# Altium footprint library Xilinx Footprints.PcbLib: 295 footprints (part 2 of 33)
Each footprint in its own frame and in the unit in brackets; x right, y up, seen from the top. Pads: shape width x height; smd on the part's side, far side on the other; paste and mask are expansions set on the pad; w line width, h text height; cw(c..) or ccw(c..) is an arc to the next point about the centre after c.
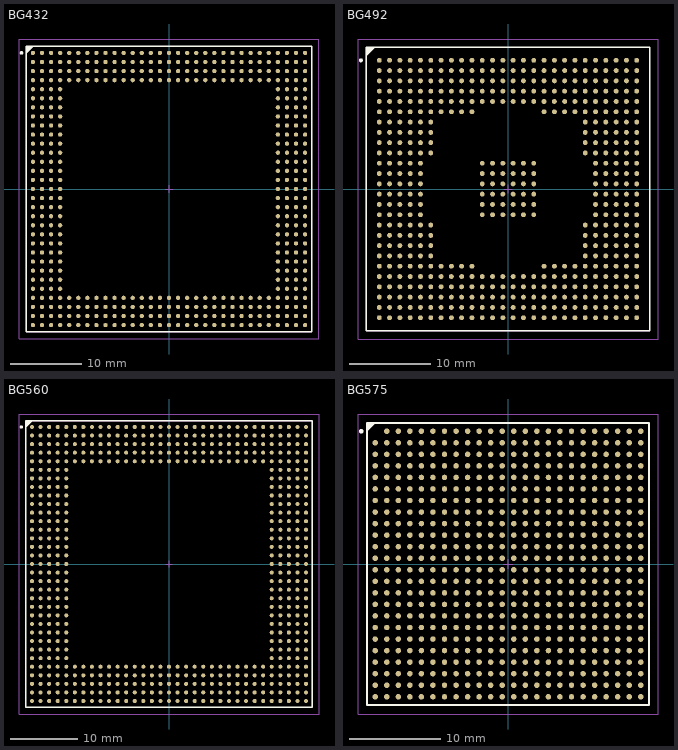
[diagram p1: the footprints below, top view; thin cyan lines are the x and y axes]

## BG432 [mm] "432-Ball Metal Ball Grid Array (BG432)"
height 1.7
pads (432):
  round 0.6 smd: A1(-19.05,19.05) A2(-17.78,19.05) A3(-16.51,19.05) A4(-15.24,19.05) A5(-13.97,19.05) A6(-12.7,19.05) A7(-11.43,19.05) A8(-10.16,19.05) A9(-8.89,19.05) A10(-7.62,19.05) A11(-6.35,19.05) A12(-5.08,19.05) A13(-3.81,19.05) A14(-2.54,19.05) A15(-1.27,19.05) A16(0,19.05) A17(1.27,19.05) A18(2.54,19.05) A19(3.81,19.05) A20(5.08,19.05) A21(6.35,19.05) A22(7.62,19.05) A23(8.89,19.05) A24(10.16,19.05) A25(11.43,19.05) A26(12.7,19.05) A27(13.97,19.05) A28(15.24,19.05) A29(16.51,19.05) A30(17.78,19.05) A31(19.05,19.05) AA1(-19.05,-6.35) AA2(-17.78,-6.35) AA3(-16.51,-6.35) AA4(-15.24,-6.35) AA28(15.24,-6.35) AA29(16.51,-6.35) AA30(17.78,-6.35) AA31(19.05,-6.35) AB1(-19.05,-7.62) AB2(-17.78,-7.62) AB3(-16.51,-7.62) AB4(-15.24,-7.62) AB28(15.24,-7.62) AB29(16.51,-7.62) AB30(17.78,-7.62) AB31(19.05,-7.62) AC1(-19.05,-8.89) AC2(-17.78,-8.89) AC3(-16.51,-8.89) AC4(-15.24,-8.89) AC28(15.24,-8.89) AC29(16.51,-8.89) AC30(17.78,-8.89) AC31(19.05,-8.89) AD1(-19.05,-10.16) AD2(-17.78,-10.16) AD3(-16.51,-10.16) AD4(-15.24,-10.16) AD28(15.24,-10.16) AD29(16.51,-10.16) AD30(17.78,-10.16) AD31(19.05,-10.16) AE1(-19.05,-11.43) AE2(-17.78,-11.43) AE3(-16.51,-11.43) AE4(-15.24,-11.43) AE28(15.24,-11.43) AE29(16.51,-11.43) AE30(17.78,-11.43) AE31(19.05,-11.43) AF1(-19.05,-12.7) AF2(-17.78,-12.7) AF3(-16.51,-12.7) AF4(-15.24,-12.7) AF28(15.24,-12.7) AF29(16.51,-12.7) AF30(17.78,-12.7) AF31(19.05,-12.7) AG1(-19.05,-13.97) AG2(-17.78,-13.97) AG3(-16.51,-13.97) AG4(-15.24,-13.97) AG28(15.24,-13.97) AG29(16.51,-13.97) AG30(17.78,-13.97) AG31(19.05,-13.97) AH1(-19.05,-15.24) AH2(-17.78,-15.24) AH3(-16.51,-15.24) AH4(-15.24,-15.24) AH5(-13.97,-15.24) AH6(-12.7,-15.24) AH7(-11.43,-15.24) AH8(-10.16,-15.24) AH9(-8.89,-15.24) AH10(-7.62,-15.24) AH11(-6.35,-15.24) AH12(-5.08,-15.24) AH13(-3.81,-15.24) AH14(-2.54,-15.24) AH15(-1.27,-15.24) AH16(0,-15.24) AH17(1.27,-15.24) AH18(2.54,-15.24) AH19(3.81,-15.24) AH20(5.08,-15.24) AH21(6.35,-15.24) AH22(7.62,-15.24) AH23(8.89,-15.24) AH24(10.16,-15.24) AH25(11.43,-15.24) AH26(12.7,-15.24) AH27(13.97,-15.24) AH28(15.24,-15.24) AH29(16.51,-15.24) AH30(17.78,-15.24) AH31(19.05,-15.24) AJ1(-19.05,-16.51) AJ2(-17.78,-16.51) AJ3(-16.51,-16.51) AJ4(-15.24,-16.51) AJ5(-13.97,-16.51) AJ6(-12.7,-16.51) AJ7(-11.43,-16.51) AJ8(-10.16,-16.51) AJ9(-8.89,-16.51) AJ10(-7.62,-16.51) AJ11(-6.35,-16.51) AJ12(-5.08,-16.51) AJ13(-3.81,-16.51) AJ14(-2.54,-16.51) AJ15(-1.27,-16.51) AJ16(0,-16.51) AJ17(1.27,-16.51) AJ18(2.54,-16.51) AJ19(3.81,-16.51) AJ20(5.08,-16.51) AJ21(6.35,-16.51) AJ22(7.62,-16.51) AJ23(8.89,-16.51) AJ24(10.16,-16.51) AJ25(11.43,-16.51) AJ26(12.7,-16.51) AJ27(13.97,-16.51) AJ28(15.24,-16.51) AJ29(16.51,-16.51) AJ30(17.78,-16.51) AJ31(19.05,-16.51) AK1(-19.05,-17.78) AK2(-17.78,-17.78) AK3(-16.51,-17.78) AK4(-15.24,-17.78) AK5(-13.97,-17.78) AK6(-12.7,-17.78) AK7(-11.43,-17.78) AK8(-10.16,-17.78) AK9(-8.89,-17.78) AK10(-7.62,-17.78) AK11(-6.35,-17.78) AK12(-5.08,-17.78) AK13(-3.81,-17.78) AK14(-2.54,-17.78) AK15(-1.27,-17.78) AK16(0,-17.78) AK17(1.27,-17.78) AK18(2.54,-17.78) AK19(3.81,-17.78) AK20(5.08,-17.78) AK21(6.35,-17.78) AK22(7.62,-17.78) AK23(8.89,-17.78) AK24(10.16,-17.78) AK25(11.43,-17.78) AK26(12.7,-17.78) AK27(13.97,-17.78) AK28(15.24,-17.78) AK29(16.51,-17.78) AK30(17.78,-17.78) AK31(19.05,-17.78) AL1(-19.05,-19.05) AL2(-17.78,-19.05) AL3(-16.51,-19.05) AL4(-15.24,-19.05) AL5(-13.97,-19.05) AL6(-12.7,-19.05) AL7(-11.43,-19.05) AL8(-10.16,-19.05) AL9(-8.89,-19.05) AL10(-7.62,-19.05) AL11(-6.35,-19.05) AL12(-5.08,-19.05) AL13(-3.81,-19.05) AL14(-2.54,-19.05) AL15(-1.27,-19.05) AL16(0,-19.05) AL17(1.27,-19.05) AL18(2.54,-19.05) AL19(3.81,-19.05) AL20(5.08,-19.05) AL21(6.35,-19.05) AL22(7.62,-19.05) AL23(8.89,-19.05) AL24(10.16,-19.05) AL25(11.43,-19.05) AL26(12.7,-19.05) AL27(13.97,-19.05) AL28(15.24,-19.05) AL29(16.51,-19.05) AL30(17.78,-19.05) AL31(19.05,-19.05) B1(-19.05,17.78) B2(-17.78,17.78) B3(-16.51,17.78) B4(-15.24,17.78) B5(-13.97,17.78) B6(-12.7,17.78) B7(-11.43,17.78) B8(-10.16,17.78) B9(-8.89,17.78) B10(-7.62,17.78) B11(-6.35,17.78) B12(-5.08,17.78) B13(-3.81,17.78) B14(-2.54,17.78) B15(-1.27,17.78) B16(0,17.78) B17(1.27,17.78) B18(2.54,17.78) B19(3.81,17.78) B20(5.08,17.78) B21(6.35,17.78) B22(7.62,17.78) B23(8.89,17.78) B24(10.16,17.78) B25(11.43,17.78) B26(12.7,17.78) B27(13.97,17.78) B28(15.24,17.78) B29(16.51,17.78) B30(17.78,17.78) B31(19.05,17.78) C1(-19.05,16.51) C2(-17.78,16.51) C3(-16.51,16.51) C4(-15.24,16.51) C5(-13.97,16.51) C6(-12.7,16.51) C7(-11.43,16.51) C8(-10.16,16.51) C9(-8.89,16.51) C10(-7.62,16.51) C11(-6.35,16.51) C12(-5.08,16.51) C13(-3.81,16.51) C14(-2.54,16.51) C15(-1.27,16.51) C16(0,16.51) C17(1.27,16.51) C18(2.54,16.51) C19(3.81,16.51) C20(5.08,16.51) C21(6.35,16.51) C22(7.62,16.51) C23(8.89,16.51) C24(10.16,16.51) C25(11.43,16.51) C26(12.7,16.51) C27(13.97,16.51) C28(15.24,16.51) C29(16.51,16.51) C30(17.78,16.51) C31(19.05,16.51) D1(-19.05,15.24) D2(-17.78,15.24) D3(-16.51,15.24) D4(-15.24,15.24) D5(-13.97,15.24) D6(-12.7,15.24) D7(-11.43,15.24) D8(-10.16,15.24) D9(-8.89,15.24) D10(-7.62,15.24) D11(-6.35,15.24) D12(-5.08,15.24) D13(-3.81,15.24) D14(-2.54,15.24) D15(-1.27,15.24) D16(0,15.24) D17(1.27,15.24) D18(2.54,15.24) D19(3.81,15.24) D20(5.08,15.24) D21(6.35,15.24) D22(7.62,15.24) D23(8.89,15.24) D24(10.16,15.24) D25(11.43,15.24) D26(12.7,15.24) D27(13.97,15.24) D28(15.24,15.24) D29(16.51,15.24) D30(17.78,15.24) D31(19.05,15.24) E1(-19.05,13.97) E2(-17.78,13.97) E3(-16.51,13.97) E4(-15.24,13.97) E28(15.24,13.97) E29(16.51,13.97) E30(17.78,13.97) E31(19.05,13.97) F1(-19.05,12.7) F2(-17.78,12.7) F3(-16.51,12.7) F4(-15.24,12.7) F28(15.24,12.7) F29(16.51,12.7) F30(17.78,12.7) F31(19.05,12.7) G1(-19.05,11.43) G2(-17.78,11.43) G3(-16.51,11.43) G4(-15.24,11.43) G28(15.24,11.43) G29(16.51,11.43) G30(17.78,11.43) G31(19.05,11.43) H1(-19.05,10.16) H2(-17.78,10.16) H3(-16.51,10.16) H4(-15.24,10.16) H28(15.24,10.16) H29(16.51,10.16) H30(17.78,10.16) H31(19.05,10.16) J1(-19.05,8.89) J2(-17.78,8.89) J3(-16.51,8.89) J4(-15.24,8.89) J28(15.24,8.89) J29(16.51,8.89) J30(17.78,8.89) J31(19.05,8.89) K1(-19.05,7.62) K2(-17.78,7.62) K3(-16.51,7.62) K4(-15.24,7.62) K28(15.24,7.62) K29(16.51,7.62) K30(17.78,7.62) K31(19.05,7.62) L1(-19.05,6.35) L2(-17.78,6.35) L3(-16.51,6.35) L4(-15.24,6.35) L28(15.24,6.35) L29(16.51,6.35) L30(17.78,6.35) L31(19.05,6.35) M1(-19.05,5.08) M2(-17.78,5.08) M3(-16.51,5.08) M4(-15.24,5.08) M28(15.24,5.08) M29(16.51,5.08) M30(17.78,5.08) M31(19.05,5.08) N1(-19.05,3.81) N2(-17.78,3.81) N3(-16.51,3.81) N4(-15.24,3.81) N28(15.24,3.81) N29(16.51,3.81) N30(17.78,3.81) N31(19.05,3.81) P1(-19.05,2.54) P2(-17.78,2.54) P3(-16.51,2.54) P4(-15.24,2.54) P28(15.24,2.54) P29(16.51,2.54) P30(17.78,2.54) P31(19.05,2.54) R1(-19.05,1.27) R2(-17.78,1.27) R3(-16.51,1.27) R4(-15.24,1.27) R28(15.24,1.27) R29(16.51,1.27) R30(17.78,1.27) R31(19.05,1.27) T1(-19.05,0) T2(-17.78,0) T3(-16.51,0) T4(-15.24,0) T28(15.24,0) T29(16.51,0) T30(17.78,0) T31(19.05,0) U1(-19.05,-1.27) U2(-17.78,-1.27) U3(-16.51,-1.27) U4(-15.24,-1.27) U28(15.24,-1.27) U29(16.51,-1.27) U30(17.78,-1.27) U31(19.05,-1.27) V1(-19.05,-2.54) V2(-17.78,-2.54) V3(-16.51,-2.54) V4(-15.24,-2.54) V28(15.24,-2.54) V29(16.51,-2.54) V30(17.78,-2.54) V31(19.05,-2.54) W1(-19.05,-3.81) W2(-17.78,-3.81) W3(-16.51,-3.81) W4(-15.24,-3.81) W28(15.24,-3.81) W29(16.51,-3.81) W30(17.78,-3.81) W31(19.05,-3.81) Y1(-19.05,-5.08) Y2(-17.78,-5.08) Y3(-16.51,-5.08) Y4(-15.24,-5.08) Y28(15.24,-5.08) Y29(16.51,-5.08) Y30(17.78,-5.08) Y31(19.05,-5.08)
Top Overlay:
  circle w0.25: c-20.65,19.05 r0.125
  region: -19.09,20 -20,19.09 -20,20
  lines w0.2: -20,19.09 -19.09,20 ; -20,-20 20,-20 20,20 -20,20 -20,-20
Mechanical 13:
  lines w0.1: -20,-20 20,-20 20,20 -20,20 -20,-20
Mechanical 15:
  lines w0.1: -0.5,0 0.5,0 ; 0,-0.5 0,0.5 ; -21,-21 21,-21 21,21 -21,21 -21,-21
3D body: height 1.7, standoff 0, extent -20,-20 20,20

## BG492 [mm] "492-Ball Plastic Ball Grid Array 1.27 mm Pitch (BG492)"
height 2.55
pads (492):
  round 0.6 smd: A1(-15.875,15.875) A2(-14.605,15.875) A3(-13.335,15.875) A4(-12.065,15.875) A5(-10.795,15.875) A6(-9.525,15.875) A7(-8.255,15.875) A8(-6.985,15.875) A9(-5.715,15.875) A10(-4.445,15.875) A11(-3.175,15.875) A12(-1.905,15.875) A13(-0.635,15.875) A14(0.635,15.875) A15(1.905,15.875) A16(3.175,15.875) A17(4.445,15.875) A18(5.715,15.875) A19(6.985,15.875) A20(8.255,15.875) A21(9.525,15.875) A22(10.795,15.875) A23(12.065,15.875) A24(13.335,15.875) A25(14.605,15.875) A26(15.875,15.875) AA1(-15.875,-9.525) AA2(-14.605,-9.525) AA3(-13.335,-9.525) AA4(-12.065,-9.525) AA5(-10.795,-9.525) AA6(-9.525,-9.525) AA7(-8.255,-9.525) AA8(-6.985,-9.525) AA9(-5.715,-9.525) AA10(-4.445,-9.525) AA17(4.445,-9.525) AA18(5.715,-9.525) AA19(6.985,-9.525) AA20(8.255,-9.525) AA21(9.525,-9.525) AA22(10.795,-9.525) AA23(12.065,-9.525) AA24(13.335,-9.525) AA25(14.605,-9.525) AA26(15.875,-9.525) AB1(-15.875,-10.795) AB2(-14.605,-10.795) AB3(-13.335,-10.795) AB4(-12.065,-10.795) AB5(-10.795,-10.795) AB6(-9.525,-10.795) AB7(-8.255,-10.795) AB8(-6.985,-10.795) AB9(-5.715,-10.795) AB10(-4.445,-10.795) AB11(-3.175,-10.795) AB12(-1.905,-10.795) AB13(-0.635,-10.795) AB14(0.635,-10.795) AB15(1.905,-10.795) AB16(3.175,-10.795) AB17(4.445,-10.795) AB18(5.715,-10.795) AB19(6.985,-10.795) AB20(8.255,-10.795) AB21(9.525,-10.795) AB22(10.795,-10.795) AB23(12.065,-10.795) AB24(13.335,-10.795) AB25(14.605,-10.795) AB26(15.875,-10.795) AC1(-15.875,-12.065) AC2(-14.605,-12.065) AC3(-13.335,-12.065) AC4(-12.065,-12.065) AC5(-10.795,-12.065) AC6(-9.525,-12.065) AC7(-8.255,-12.065) AC8(-6.985,-12.065) AC9(-5.715,-12.065) AC10(-4.445,-12.065) AC11(-3.175,-12.065) AC12(-1.905,-12.065) AC13(-0.635,-12.065) AC14(0.635,-12.065) AC15(1.905,-12.065) AC16(3.175,-12.065) AC17(4.445,-12.065) AC18(5.715,-12.065) AC19(6.985,-12.065) AC20(8.255,-12.065) AC21(9.525,-12.065) AC22(10.795,-12.065) AC23(12.065,-12.065) AC24(13.335,-12.065) AC25(14.605,-12.065) AC26(15.875,-12.065) AD1(-15.875,-13.335) AD2(-14.605,-13.335) AD3(-13.335,-13.335) AD4(-12.065,-13.335) AD5(-10.795,-13.335) AD6(-9.525,-13.335) AD7(-8.255,-13.335) AD8(-6.985,-13.335) AD9(-5.715,-13.335) AD10(-4.445,-13.335) AD11(-3.175,-13.335) AD12(-1.905,-13.335) AD13(-0.635,-13.335) AD14(0.635,-13.335) AD15(1.905,-13.335) AD16(3.175,-13.335) AD17(4.445,-13.335) AD18(5.715,-13.335) AD19(6.985,-13.335) AD20(8.255,-13.335) AD21(9.525,-13.335) AD22(10.795,-13.335) AD23(12.065,-13.335) AD24(13.335,-13.335) AD25(14.605,-13.335) AD26(15.875,-13.335) AE1(-15.875,-14.605) AE2(-14.605,-14.605) AE3(-13.335,-14.605) AE4(-12.065,-14.605) AE5(-10.795,-14.605) AE6(-9.525,-14.605) AE7(-8.255,-14.605) AE8(-6.985,-14.605) AE9(-5.715,-14.605) AE10(-4.445,-14.605) AE11(-3.175,-14.605) AE12(-1.905,-14.605) AE13(-0.635,-14.605) AE14(0.635,-14.605) AE15(1.905,-14.605) AE16(3.175,-14.605) AE17(4.445,-14.605) AE18(5.715,-14.605) AE19(6.985,-14.605) AE20(8.255,-14.605) AE21(9.525,-14.605) AE22(10.795,-14.605) AE23(12.065,-14.605) AE24(13.335,-14.605) AE25(14.605,-14.605) AE26(15.875,-14.605) AF1(-15.875,-15.875) AF2(-14.605,-15.875) AF3(-13.335,-15.875) AF4(-12.065,-15.875) AF5(-10.795,-15.875) AF6(-9.525,-15.875) AF7(-8.255,-15.875) AF8(-6.985,-15.875) AF9(-5.715,-15.875) AF10(-4.445,-15.875) AF11(-3.175,-15.875) AF12(-1.905,-15.875) AF13(-0.635,-15.875) AF14(0.635,-15.875) AF15(1.905,-15.875) AF16(3.175,-15.875) AF17(4.445,-15.875) AF18(5.715,-15.875) AF19(6.985,-15.875) AF20(8.255,-15.875) AF21(9.525,-15.875) AF22(10.795,-15.875) AF23(12.065,-15.875) AF24(13.335,-15.875) AF25(14.605,-15.875) AF26(15.875,-15.875) B1(-15.875,14.605) B2(-14.605,14.605) B3(-13.335,14.605) B4(-12.065,14.605) B5(-10.795,14.605) B6(-9.525,14.605) B7(-8.255,14.605) B8(-6.985,14.605) B9(-5.715,14.605) B10(-4.445,14.605) B11(-3.175,14.605) B12(-1.905,14.605) B13(-0.635,14.605) B14(0.635,14.605) B15(1.905,14.605) B16(3.175,14.605) B17(4.445,14.605) B18(5.715,14.605) B19(6.985,14.605) B20(8.255,14.605) B21(9.525,14.605) B22(10.795,14.605) B23(12.065,14.605) B24(13.335,14.605) B25(14.605,14.605) B26(15.875,14.605) C1(-15.875,13.335) C2(-14.605,13.335) C3(-13.335,13.335) C4(-12.065,13.335) C5(-10.795,13.335) C6(-9.525,13.335) C7(-8.255,13.335) C8(-6.985,13.335) C9(-5.715,13.335) C10(-4.445,13.335) C11(-3.175,13.335) C12(-1.905,13.335) C13(-0.635,13.335) C14(0.635,13.335) C15(1.905,13.335) C16(3.175,13.335) C17(4.445,13.335) C18(5.715,13.335) C19(6.985,13.335) C20(8.255,13.335) C21(9.525,13.335) C22(10.795,13.335) C23(12.065,13.335) C24(13.335,13.335) C25(14.605,13.335) C26(15.875,13.335) D1(-15.875,12.065) D2(-14.605,12.065) D3(-13.335,12.065) D4(-12.065,12.065) D5(-10.795,12.065) D6(-9.525,12.065) D7(-8.255,12.065) D8(-6.985,12.065) D9(-5.715,12.065) D10(-4.445,12.065) D11(-3.175,12.065) D12(-1.905,12.065) D13(-0.635,12.065) D14(0.635,12.065) D15(1.905,12.065) D16(3.175,12.065) D17(4.445,12.065) D18(5.715,12.065) D19(6.985,12.065) D20(8.255,12.065) D21(9.525,12.065) D22(10.795,12.065) D23(12.065,12.065) D24(13.335,12.065) D25(14.605,12.065) D26(15.875,12.065) E1(-15.875,10.795) E2(-14.605,10.795) E3(-13.335,10.795) E4(-12.065,10.795) E5(-10.795,10.795) E6(-9.525,10.795) E7(-8.255,10.795) E8(-6.985,10.795) E9(-5.715,10.795) E10(-4.445,10.795) E11(-3.175,10.795) E12(-1.905,10.795) E13(-0.635,10.795) E14(0.635,10.795) E15(1.905,10.795) E16(3.175,10.795) E17(4.445,10.795) E18(5.715,10.795) E19(6.985,10.795) E20(8.255,10.795) E21(9.525,10.795) E22(10.795,10.795) E23(12.065,10.795) E24(13.335,10.795) E25(14.605,10.795) E26(15.875,10.795) F1(-15.875,9.525) F2(-14.605,9.525) F3(-13.335,9.525) F4(-12.065,9.525) F5(-10.795,9.525) F6(-9.525,9.525) F7(-8.255,9.525) F8(-6.985,9.525) F9(-5.715,9.525) F10(-4.445,9.525) F17(4.445,9.525) F18(5.715,9.525) F19(6.985,9.525) F20(8.255,9.525) F21(9.525,9.525) F22(10.795,9.525) F23(12.065,9.525) F24(13.335,9.525) F25(14.605,9.525) F26(15.875,9.525) G1(-15.875,8.255) G2(-14.605,8.255) G3(-13.335,8.255) G4(-12.065,8.255) G5(-10.795,8.255) G6(-9.525,8.255) G21(9.525,8.255) G22(10.795,8.255) G23(12.065,8.255) G24(13.335,8.255) G25(14.605,8.255) G26(15.875,8.255) H1(-15.875,6.985) H2(-14.605,6.985) H3(-13.335,6.985) H4(-12.065,6.985) H5(-10.795,6.985) H6(-9.525,6.985) H21(9.525,6.985) H22(10.795,6.985) H23(12.065,6.985) H24(13.335,6.985) H25(14.605,6.985) H26(15.875,6.985) J1(-15.875,5.715) J2(-14.605,5.715) J3(-13.335,5.715) J4(-12.065,5.715) J5(-10.795,5.715) J6(-9.525,5.715) J21(9.525,5.715) J22(10.795,5.715) J23(12.065,5.715) J24(13.335,5.715) J25(14.605,5.715) J26(15.875,5.715) K1(-15.875,4.445) K2(-14.605,4.445) K3(-13.335,4.445) K4(-12.065,4.445) K5(-10.795,4.445) K6(-9.525,4.445) K21(9.525,4.445) K22(10.795,4.445) K23(12.065,4.445) K24(13.335,4.445) K25(14.605,4.445) K26(15.875,4.445) L1(-15.875,3.175) L2(-14.605,3.175) L3(-13.335,3.175) L4(-12.065,3.175) L5(-10.795,3.175) L11(-3.175,3.175) L12(-1.905,3.175) L13(-0.635,3.175) L14(0.635,3.175) L15(1.905,3.175) L16(3.175,3.175) L22(10.795,3.175) L23(12.065,3.175) L24(13.335,3.175) L25(14.605,3.175) L26(15.875,3.175) M1(-15.875,1.905) M2(-14.605,1.905) M3(-13.335,1.905) M4(-12.065,1.905) M5(-10.795,1.905) M11(-3.175,1.905) M12(-1.905,1.905) M13(-0.635,1.905) M14(0.635,1.905) M15(1.905,1.905) M16(3.175,1.905) M22(10.795,1.905) M23(12.065,1.905) M24(13.335,1.905) M25(14.605,1.905) M26(15.875,1.905) N1(-15.875,0.635) N2(-14.605,0.635) N3(-13.335,0.635) N4(-12.065,0.635) N5(-10.795,0.635) N11(-3.175,0.635) N12(-1.905,0.635) N13(-0.635,0.635) N14(0.635,0.635) N15(1.905,0.635) N16(3.175,0.635) N22(10.795,0.635) N23(12.065,0.635) N24(13.335,0.635) N25(14.605,0.635) N26(15.875,0.635) P1(-15.875,-0.635) P2(-14.605,-0.635) P3(-13.335,-0.635) P4(-12.065,-0.635) P5(-10.795,-0.635) P11(-3.175,-0.635) P12(-1.905,-0.635) P13(-0.635,-0.635) P14(0.635,-0.635) P15(1.905,-0.635) P16(3.175,-0.635) P22(10.795,-0.635) P23(12.065,-0.635) P24(13.335,-0.635) P25(14.605,-0.635) P26(15.875,-0.635) R1(-15.875,-1.905) R2(-14.605,-1.905) R3(-13.335,-1.905) R4(-12.065,-1.905) R5(-10.795,-1.905) R11(-3.175,-1.905) R12(-1.905,-1.905) R13(-0.635,-1.905) R14(0.635,-1.905) R15(1.905,-1.905) R16(3.175,-1.905) R22(10.795,-1.905) R23(12.065,-1.905) R24(13.335,-1.905) R25(14.605,-1.905) R26(15.875,-1.905) T1(-15.875,-3.175) T2(-14.605,-3.175) T3(-13.335,-3.175) T4(-12.065,-3.175) T5(-10.795,-3.175) T11(-3.175,-3.175) T12(-1.905,-3.175) T13(-0.635,-3.175) T14(0.635,-3.175) T15(1.905,-3.175) T16(3.175,-3.175) T22(10.795,-3.175) T23(12.065,-3.175) T24(13.335,-3.175) T25(14.605,-3.175) T26(15.875,-3.175) U1(-15.875,-4.445) U2(-14.605,-4.445) U3(-13.335,-4.445) U4(-12.065,-4.445) U5(-10.795,-4.445) U6(-9.525,-4.445) U21(9.525,-4.445) U22(10.795,-4.445) U23(12.065,-4.445) U24(13.335,-4.445) U25(14.605,-4.445) U26(15.875,-4.445) V1(-15.875,-5.715) V2(-14.605,-5.715) V3(-13.335,-5.715) V4(-12.065,-5.715) V5(-10.795,-5.715) V6(-9.525,-5.715) V21(9.525,-5.715) V22(10.795,-5.715) V23(12.065,-5.715) V24(13.335,-5.715) V25(14.605,-5.715) V26(15.875,-5.715) W1(-15.875,-6.985) W2(-14.605,-6.985) W3(-13.335,-6.985) W4(-12.065,-6.985) W5(-10.795,-6.985) W6(-9.525,-6.985) W21(9.525,-6.985) W22(10.795,-6.985) W23(12.065,-6.985) W24(13.335,-6.985) W25(14.605,-6.985) W26(15.875,-6.985) Y1(-15.875,-8.255) Y2(-14.605,-8.255) Y3(-13.335,-8.255) Y4(-12.065,-8.255) Y5(-10.795,-8.255) Y6(-9.525,-8.255) Y21(9.525,-8.255) Y22(10.795,-8.255) Y23(12.065,-8.255) Y24(13.335,-8.255) Y25(14.605,-8.255) Y26(15.875,-8.255)
Top Overlay:
  circle w0.25: c-18.15,15.875 r0.125
  region: -16.5,17.5 -17.5,16.5 -17.5,17.5
  lines w0.2: -17.5,16.5 -16.5,17.5 ; -17.5,-17.5 17.5,-17.5 17.5,17.5 -17.5,17.5 -17.5,-17.5
Mechanical 13:
  lines w0.1: -17.5,-17.5 17.5,-17.5 17.5,17.5 -17.5,17.5 -17.5,-17.5
Mechanical 15:
  lines w0.1: -0.5,0 0.5,0 ; 0,-0.5 0,0.5 ; -18.5,-18.5 18.5,-18.5 18.5,18.5 -18.5,18.5 -18.5,-18.5
3D body: height 2.55, standoff 0, extent -17.5,-17.5 17.5,17.5

## BG560 [mm] "560-Ball Metal Ball Grid Array (BG560)"
height 1.7
pads (560):
  round 0.6 smd: A1(-20.32,20.32) A2(-19.05,20.32) A3(-17.78,20.32) A4(-16.51,20.32) A5(-15.24,20.32) A6(-13.97,20.32) A7(-12.7,20.32) A8(-11.43,20.32) A9(-10.16,20.32) A10(-8.89,20.32) A11(-7.62,20.32) A12(-6.35,20.32) A13(-5.08,20.32) A14(-3.81,20.32) A15(-2.54,20.32) A16(-1.27,20.32) A17(0,20.32) A18(1.27,20.32) A19(2.54,20.32) A20(3.81,20.32) A21(5.08,20.32) A22(6.35,20.32) A23(7.62,20.32) A24(8.89,20.32) A25(10.16,20.32) A26(11.43,20.32) A27(12.7,20.32) A28(13.97,20.32) A29(15.24,20.32) A30(16.51,20.32) A31(17.78,20.32) A32(19.05,20.32) A33(20.32,20.32) AA1(-20.32,-5.08) AA2(-19.05,-5.08) AA3(-17.78,-5.08) AA4(-16.51,-5.08) AA5(-15.24,-5.08) AA29(15.24,-5.08) AA30(16.51,-5.08) AA31(17.78,-5.08) AA32(19.05,-5.08) AA33(20.32,-5.08) AB1(-20.32,-6.35) AB2(-19.05,-6.35) AB3(-17.78,-6.35) AB4(-16.51,-6.35) AB5(-15.24,-6.35) AB29(15.24,-6.35) AB30(16.51,-6.35) AB31(17.78,-6.35) AB32(19.05,-6.35) AB33(20.32,-6.35) AC1(-20.32,-7.62) AC2(-19.05,-7.62) AC3(-17.78,-7.62) AC4(-16.51,-7.62) AC5(-15.24,-7.62) AC29(15.24,-7.62) AC30(16.51,-7.62) AC31(17.78,-7.62) AC32(19.05,-7.62) AC33(20.32,-7.62) AD1(-20.32,-8.89) AD2(-19.05,-8.89) AD3(-17.78,-8.89) AD4(-16.51,-8.89) AD5(-15.24,-8.89) AD29(15.24,-8.89) AD30(16.51,-8.89) AD31(17.78,-8.89) AD32(19.05,-8.89) AD33(20.32,-8.89) AE1(-20.32,-10.16) AE2(-19.05,-10.16) AE3(-17.78,-10.16) AE4(-16.51,-10.16) AE5(-15.24,-10.16) AE29(15.24,-10.16) AE30(16.51,-10.16) AE31(17.78,-10.16) AE32(19.05,-10.16) AE33(20.32,-10.16) AF1(-20.32,-11.43) AF2(-19.05,-11.43) AF3(-17.78,-11.43) AF4(-16.51,-11.43) AF5(-15.24,-11.43) AF29(15.24,-11.43) AF30(16.51,-11.43) AF31(17.78,-11.43) AF32(19.05,-11.43) AF33(20.32,-11.43) AG1(-20.32,-12.7) AG2(-19.05,-12.7) AG3(-17.78,-12.7) AG4(-16.51,-12.7) AG5(-15.24,-12.7) AG29(15.24,-12.7) AG30(16.51,-12.7) AG31(17.78,-12.7) AG32(19.05,-12.7) AG33(20.32,-12.7) AH1(-20.32,-13.97) AH2(-19.05,-13.97) AH3(-17.78,-13.97) AH4(-16.51,-13.97) AH5(-15.24,-13.97) AH29(15.24,-13.97) AH30(16.51,-13.97) AH31(17.78,-13.97) AH32(19.05,-13.97) AH33(20.32,-13.97) AJ1(-20.32,-15.24) AJ2(-19.05,-15.24) AJ3(-17.78,-15.24) AJ4(-16.51,-15.24) AJ5(-15.24,-15.24) AJ6(-13.97,-15.24) AJ7(-12.7,-15.24) AJ8(-11.43,-15.24) AJ9(-10.16,-15.24) AJ10(-8.89,-15.24) AJ11(-7.62,-15.24) AJ12(-6.35,-15.24) AJ13(-5.08,-15.24) AJ14(-3.81,-15.24) AJ15(-2.54,-15.24) AJ16(-1.27,-15.24) AJ17(0,-15.24) AJ18(1.27,-15.24) AJ19(2.54,-15.24) AJ20(3.81,-15.24) AJ21(5.08,-15.24) AJ22(6.35,-15.24) AJ23(7.62,-15.24) AJ24(8.89,-15.24) AJ25(10.16,-15.24) AJ26(11.43,-15.24) AJ27(12.7,-15.24) AJ28(13.97,-15.24) AJ29(15.24,-15.24) AJ30(16.51,-15.24) AJ31(17.78,-15.24) AJ32(19.05,-15.24) AJ33(20.32,-15.24) AK1(-20.32,-16.51) AK2(-19.05,-16.51) AK3(-17.78,-16.51) AK4(-16.51,-16.51) AK5(-15.24,-16.51) AK6(-13.97,-16.51) AK7(-12.7,-16.51) AK8(-11.43,-16.51) AK9(-10.16,-16.51) AK10(-8.89,-16.51) AK11(-7.62,-16.51) AK12(-6.35,-16.51) AK13(-5.08,-16.51) AK14(-3.81,-16.51) AK15(-2.54,-16.51) AK16(-1.27,-16.51) AK17(0,-16.51) AK18(1.27,-16.51) AK19(2.54,-16.51) AK20(3.81,-16.51) AK21(5.08,-16.51) AK22(6.35,-16.51) AK23(7.62,-16.51) AK24(8.89,-16.51) AK25(10.16,-16.51) AK26(11.43,-16.51) AK27(12.7,-16.51) AK28(13.97,-16.51) AK29(15.24,-16.51) AK30(16.51,-16.51) AK31(17.78,-16.51) AK32(19.05,-16.51) AK33(20.32,-16.51) AL1(-20.32,-17.78) AL2(-19.05,-17.78) AL3(-17.78,-17.78) AL4(-16.51,-17.78) AL5(-15.24,-17.78) AL6(-13.97,-17.78) AL7(-12.7,-17.78) AL8(-11.43,-17.78) AL9(-10.16,-17.78) AL10(-8.89,-17.78) AL11(-7.62,-17.78) AL12(-6.35,-17.78) AL13(-5.08,-17.78) AL14(-3.81,-17.78) AL15(-2.54,-17.78) AL16(-1.27,-17.78) AL17(0,-17.78) AL18(1.27,-17.78) AL19(2.54,-17.78) AL20(3.81,-17.78) AL21(5.08,-17.78) AL22(6.35,-17.78) AL23(7.62,-17.78) AL24(8.89,-17.78) AL25(10.16,-17.78) AL26(11.43,-17.78) AL27(12.7,-17.78) AL28(13.97,-17.78) AL29(15.24,-17.78) AL30(16.51,-17.78) AL31(17.78,-17.78) AL32(19.05,-17.78) AL33(20.32,-17.78) AM1(-20.32,-19.05) AM2(-19.05,-19.05) AM3(-17.78,-19.05) AM4(-16.51,-19.05) AM5(-15.24,-19.05) AM6(-13.97,-19.05) AM7(-12.7,-19.05) AM8(-11.43,-19.05) AM9(-10.16,-19.05) AM10(-8.89,-19.05) AM11(-7.62,-19.05) AM12(-6.35,-19.05) AM13(-5.08,-19.05) AM14(-3.81,-19.05) AM15(-2.54,-19.05) AM16(-1.27,-19.05) AM17(0,-19.05) AM18(1.27,-19.05) AM19(2.54,-19.05) AM20(3.81,-19.05) AM21(5.08,-19.05) AM22(6.35,-19.05) AM23(7.62,-19.05) AM24(8.89,-19.05) AM25(10.16,-19.05) AM26(11.43,-19.05) AM27(12.7,-19.05) AM28(13.97,-19.05) AM29(15.24,-19.05) AM30(16.51,-19.05) AM31(17.78,-19.05) AM32(19.05,-19.05) AM33(20.32,-19.05) AN1(-20.32,-20.32) AN2(-19.05,-20.32) AN3(-17.78,-20.32) AN4(-16.51,-20.32) AN5(-15.24,-20.32) AN6(-13.97,-20.32) AN7(-12.7,-20.32) AN8(-11.43,-20.32) AN9(-10.16,-20.32) AN10(-8.89,-20.32) AN11(-7.62,-20.32) AN12(-6.35,-20.32) AN13(-5.08,-20.32) AN14(-3.81,-20.32) AN15(-2.54,-20.32) AN16(-1.27,-20.32) AN17(0,-20.32) AN18(1.27,-20.32) AN19(2.54,-20.32) AN20(3.81,-20.32) AN21(5.08,-20.32) AN22(6.35,-20.32) AN23(7.62,-20.32) AN24(8.89,-20.32) AN25(10.16,-20.32) AN26(11.43,-20.32) AN27(12.7,-20.32) AN28(13.97,-20.32) AN29(15.24,-20.32) AN30(16.51,-20.32) AN31(17.78,-20.32) AN32(19.05,-20.32) AN33(20.32,-20.32) B1(-20.32,19.05) B2(-19.05,19.05) B3(-17.78,19.05) B4(-16.51,19.05) B5(-15.24,19.05) B6(-13.97,19.05) B7(-12.7,19.05) B8(-11.43,19.05) B9(-10.16,19.05) B10(-8.89,19.05) B11(-7.62,19.05) B12(-6.35,19.05) B13(-5.08,19.05) B14(-3.81,19.05) B15(-2.54,19.05) B16(-1.27,19.05) B17(0,19.05) B18(1.27,19.05) B19(2.54,19.05) B20(3.81,19.05) B21(5.08,19.05) B22(6.35,19.05) B23(7.62,19.05) B24(8.89,19.05) B25(10.16,19.05) B26(11.43,19.05) B27(12.7,19.05) B28(13.97,19.05) B29(15.24,19.05) B30(16.51,19.05) B31(17.78,19.05) B32(19.05,19.05) B33(20.32,19.05) C1(-20.32,17.78) C2(-19.05,17.78) C3(-17.78,17.78) C4(-16.51,17.78) C5(-15.24,17.78) C6(-13.97,17.78) C7(-12.7,17.78) C8(-11.43,17.78) C9(-10.16,17.78) C10(-8.89,17.78) C11(-7.62,17.78) C12(-6.35,17.78) C13(-5.08,17.78) C14(-3.81,17.78) C15(-2.54,17.78) C16(-1.27,17.78) C17(0,17.78) C18(1.27,17.78) C19(2.54,17.78) C20(3.81,17.78) C21(5.08,17.78) C22(6.35,17.78) C23(7.62,17.78) C24(8.89,17.78) C25(10.16,17.78) C26(11.43,17.78) C27(12.7,17.78) C28(13.97,17.78) C29(15.24,17.78) C30(16.51,17.78) C31(17.78,17.78) C32(19.05,17.78) C33(20.32,17.78) D1(-20.32,16.51) D2(-19.05,16.51) D3(-17.78,16.51) D4(-16.51,16.51) D5(-15.24,16.51) D6(-13.97,16.51) D7(-12.7,16.51) D8(-11.43,16.51) D9(-10.16,16.51) D10(-8.89,16.51) D11(-7.62,16.51) D12(-6.35,16.51) D13(-5.08,16.51) D14(-3.81,16.51) D15(-2.54,16.51) D16(-1.27,16.51) D17(0,16.51) D18(1.27,16.51) D19(2.54,16.51) D20(3.81,16.51) D21(5.08,16.51) D22(6.35,16.51) D23(7.62,16.51) D24(8.89,16.51) D25(10.16,16.51) D26(11.43,16.51) D27(12.7,16.51) D28(13.97,16.51) D29(15.24,16.51) D30(16.51,16.51) D31(17.78,16.51) D32(19.05,16.51) D33(20.32,16.51) E1(-20.32,15.24) E2(-19.05,15.24) E3(-17.78,15.24) E4(-16.51,15.24) E5(-15.24,15.24) E6(-13.97,15.24) E7(-12.7,15.24) E8(-11.43,15.24) E9(-10.16,15.24) E10(-8.89,15.24) E11(-7.62,15.24) E12(-6.35,15.24) E13(-5.08,15.24) E14(-3.81,15.24) E15(-2.54,15.24) E16(-1.27,15.24) E17(0,15.24) E18(1.27,15.24) E19(2.54,15.24) E20(3.81,15.24) E21(5.08,15.24) E22(6.35,15.24) E23(7.62,15.24) E24(8.89,15.24) E25(10.16,15.24) E26(11.43,15.24) E27(12.7,15.24) E28(13.97,15.24) E29(15.24,15.24) E30(16.51,15.24) E31(17.78,15.24) E32(19.05,15.24) E33(20.32,15.24) F1(-20.32,13.97) F2(-19.05,13.97) F3(-17.78,13.97) F4(-16.51,13.97) F5(-15.24,13.97) F29(15.24,13.97) F30(16.51,13.97) F31(17.78,13.97) F32(19.05,13.97) F33(20.32,13.97) G1(-20.32,12.7) G2(-19.05,12.7) G3(-17.78,12.7) G4(-16.51,12.7) G5(-15.24,12.7) G29(15.24,12.7) G30(16.51,12.7) G31(17.78,12.7) G32(19.05,12.7) G33(20.32,12.7) H1(-20.32,11.43) H2(-19.05,11.43) H3(-17.78,11.43) H4(-16.51,11.43) H5(-15.24,11.43) H29(15.24,11.43) H30(16.51,11.43) H31(17.78,11.43) H32(19.05,11.43) H33(20.32,11.43) J1(-20.32,10.16) J2(-19.05,10.16) J3(-17.78,10.16) J4(-16.51,10.16) J5(-15.24,10.16) J29(15.24,10.16) J30(16.51,10.16) J31(17.78,10.16) J32(19.05,10.16) J33(20.32,10.16) K1(-20.32,8.89) K2(-19.05,8.89) K3(-17.78,8.89) K4(-16.51,8.89) K5(-15.24,8.89) K29(15.24,8.89) K30(16.51,8.89) K31(17.78,8.89) K32(19.05,8.89) K33(20.32,8.89) L1(-20.32,7.62) L2(-19.05,7.62) L3(-17.78,7.62) L4(-16.51,7.62) L5(-15.24,7.62) L29(15.24,7.62) L30(16.51,7.62) L31(17.78,7.62) L32(19.05,7.62) L33(20.32,7.62) M1(-20.32,6.35) M2(-19.05,6.35) M3(-17.78,6.35) M4(-16.51,6.35) M5(-15.24,6.35) M29(15.24,6.35) M30(16.51,6.35) M31(17.78,6.35) M32(19.05,6.35) M33(20.32,6.35) N1(-20.32,5.08) N2(-19.05,5.08) N3(-17.78,5.08) N4(-16.51,5.08) N5(-15.24,5.08) N29(15.24,5.08) N30(16.51,5.08) N31(17.78,5.08) N32(19.05,5.08) N33(20.32,5.08) P1(-20.32,3.81) P2(-19.05,3.81) P3(-17.78,3.81) P4(-16.51,3.81) P5(-15.24,3.81) P29(15.24,3.81) P30(16.51,3.81) P31(17.78,3.81) P32(19.05,3.81) P33(20.32,3.81) R1(-20.32,2.54) R2(-19.05,2.54) R3(-17.78,2.54) R4(-16.51,2.54) R5(-15.24,2.54) R29(15.24,2.54) R30(16.51,2.54) R31(17.78,2.54) R32(19.05,2.54) R33(20.32,2.54) T1(-20.32,1.27) T2(-19.05,1.27) T3(-17.78,1.27) T4(-16.51,1.27) T5(-15.24,1.27) T29(15.24,1.27) T30(16.51,1.27) T31(17.78,1.27) T32(19.05,1.27) T33(20.32,1.27) U1(-20.32,0) U2(-19.05,0) U3(-17.78,0) U4(-16.51,0) U5(-15.24,0) U29(15.24,0) U30(16.51,0) U31(17.78,0) U32(19.05,0) U33(20.32,0) V1(-20.32,-1.27) V2(-19.05,-1.27) V3(-17.78,-1.27) V4(-16.51,-1.27) V5(-15.24,-1.27) V29(15.24,-1.27) V30(16.51,-1.27) V31(17.78,-1.27) V32(19.05,-1.27) V33(20.32,-1.27) W1(-20.32,-2.54) W2(-19.05,-2.54) W3(-17.78,-2.54) W4(-16.51,-2.54) W5(-15.24,-2.54) W29(15.24,-2.54) W30(16.51,-2.54) W31(17.78,-2.54) W32(19.05,-2.54) W33(20.32,-2.54) Y1(-20.32,-3.81) Y2(-19.05,-3.81) Y3(-17.78,-3.81) Y4(-16.51,-3.81) Y5(-15.24,-3.81) Y29(15.24,-3.81) Y30(16.51,-3.81) Y31(17.78,-3.81) Y32(19.05,-3.81) Y33(20.32,-3.81)
Top Overlay:
  circle w0.25: c-21.9,20.32 r0.125
  region: -20.38,21.25 -21.25,20.38 -21.25,21.25
  lines w0.2: -21.25,20.38 -20.38,21.25 ; -21.25,-21.25 -21.25,21.25 21.25,21.25 21.25,-21.25 -21.25,-21.25
Mechanical 13:
  lines w0.1: -21.25,-21.25 -21.25,21.25 21.25,21.25 21.25,-21.25 -21.25,-21.25
Mechanical 15:
  lines w0.1: -0.5,0 0.5,0 ; 0,-0.5 0,0.5 ; -22.25,-22.25 -22.25,22.25 22.25,22.25 22.25,-22.25 -22.25,-22.25
3D body: height 1.7, standoff 0, extent -21.25,-21.25 21.25,21.25

## BG575 [mm] "575-Ball Molded Ball Grid Array (BG575)"
height 2.6
pads (575):
  round 0.6 smd: A2(-13.335,14.605) A3(-12.065,14.605) A4(-10.795,14.605) A5(-9.525,14.605) A6(-8.255,14.605) A7(-6.985,14.605) A8(-5.715,14.605) A9(-4.445,14.605) A10(-3.175,14.605) A11(-1.905,14.605) A12(-0.635,14.605) A13(0.635,14.605) A14(1.905,14.605) A15(3.175,14.605) A16(4.445,14.605) A17(5.715,14.605) A18(6.985,14.605) A19(8.255,14.605) A20(9.525,14.605) A21(10.795,14.605) A22(12.065,14.605) A23(13.335,14.605) A24(14.605,14.605) AA1(-14.605,-10.795) AA2(-13.335,-10.795) AA3(-12.065,-10.795) AA4(-10.795,-10.795) AA5(-9.525,-10.795) AA6(-8.255,-10.795) AA7(-6.985,-10.795) AA8(-5.715,-10.795) AA9(-4.445,-10.795) AA10(-3.175,-10.795) AA11(-1.905,-10.795) AA12(-0.635,-10.795) AA13(0.635,-10.795) AA14(1.905,-10.795) AA15(3.175,-10.795) AA16(4.445,-10.795) AA17(5.715,-10.795) AA18(6.985,-10.795) AA19(8.255,-10.795) AA20(9.525,-10.795) AA21(10.795,-10.795) AA22(12.065,-10.795) AA23(13.335,-10.795) AA24(14.605,-10.795) AB1(-14.605,-12.065) AB2(-13.335,-12.065) AB3(-12.065,-12.065) AB4(-10.795,-12.065) AB5(-9.525,-12.065) AB6(-8.255,-12.065) AB7(-6.985,-12.065) AB8(-5.715,-12.065) AB9(-4.445,-12.065) AB10(-3.175,-12.065) AB11(-1.905,-12.065) AB12(-0.635,-12.065) AB13(0.635,-12.065) AB14(1.905,-12.065) AB15(3.175,-12.065) AB16(4.445,-12.065) AB17(5.715,-12.065) AB18(6.985,-12.065) AB19(8.255,-12.065) AB20(9.525,-12.065) AB21(10.795,-12.065) AB22(12.065,-12.065) AB23(13.335,-12.065) AB24(14.605,-12.065) AC1(-14.605,-13.335) AC2(-13.335,-13.335) AC3(-12.065,-13.335) AC4(-10.795,-13.335) AC5(-9.525,-13.335) AC6(-8.255,-13.335) AC7(-6.985,-13.335) AC8(-5.715,-13.335) AC9(-4.445,-13.335) AC10(-3.175,-13.335) AC11(-1.905,-13.335) AC12(-0.635,-13.335) AC13(0.635,-13.335) AC14(1.905,-13.335) AC15(3.175,-13.335) AC16(4.445,-13.335) AC17(5.715,-13.335) AC18(6.985,-13.335) AC19(8.255,-13.335) AC20(9.525,-13.335) AC21(10.795,-13.335) AC22(12.065,-13.335) AC23(13.335,-13.335) AC24(14.605,-13.335) AD1(-14.605,-14.605) AD2(-13.335,-14.605) AD3(-12.065,-14.605) AD4(-10.795,-14.605) AD5(-9.525,-14.605) AD6(-8.255,-14.605) AD7(-6.985,-14.605) AD8(-5.715,-14.605) AD9(-4.445,-14.605) AD10(-3.175,-14.605) AD11(-1.905,-14.605) AD12(-0.635,-14.605) AD13(0.635,-14.605) AD14(1.905,-14.605) AD15(3.175,-14.605) AD16(4.445,-14.605) AD17(5.715,-14.605) AD18(6.985,-14.605) AD19(8.255,-14.605) AD20(9.525,-14.605) AD21(10.795,-14.605) AD22(12.065,-14.605) AD23(13.335,-14.605) AD24(14.605,-14.605) B1(-14.605,13.335) B2(-13.335,13.335) B3(-12.065,13.335) B4(-10.795,13.335) B5(-9.525,13.335) B6(-8.255,13.335) B7(-6.985,13.335) B8(-5.715,13.335) B9(-4.445,13.335) B10(-3.175,13.335) B11(-1.905,13.335) B12(-0.635,13.335) B13(0.635,13.335) B14(1.905,13.335) B15(3.175,13.335) B16(4.445,13.335) B17(5.715,13.335) B18(6.985,13.335) B19(8.255,13.335) B20(9.525,13.335) B21(10.795,13.335) B22(12.065,13.335) B23(13.335,13.335) B24(14.605,13.335) C1(-14.605,12.065) C2(-13.335,12.065) C3(-12.065,12.065) C4(-10.795,12.065) C5(-9.525,12.065) C6(-8.255,12.065) C7(-6.985,12.065) C8(-5.715,12.065) C9(-4.445,12.065) C10(-3.175,12.065) C11(-1.905,12.065) C12(-0.635,12.065) C13(0.635,12.065) C14(1.905,12.065) C15(3.175,12.065) C16(4.445,12.065) C17(5.715,12.065) C18(6.985,12.065) C19(8.255,12.065) C20(9.525,12.065) C21(10.795,12.065) C22(12.065,12.065) C23(13.335,12.065) C24(14.605,12.065) D1(-14.605,10.795) D2(-13.335,10.795) D3(-12.065,10.795) D4(-10.795,10.795) D5(-9.525,10.795) D6(-8.255,10.795) D7(-6.985,10.795) D8(-5.715,10.795) D9(-4.445,10.795) D10(-3.175,10.795) D11(-1.905,10.795) D12(-0.635,10.795) D13(0.635,10.795) D14(1.905,10.795) D15(3.175,10.795) D16(4.445,10.795) D17(5.715,10.795) D18(6.985,10.795) D19(8.255,10.795) D20(9.525,10.795) D21(10.795,10.795) D22(12.065,10.795) D23(13.335,10.795) D24(14.605,10.795) E1(-14.605,9.525) E2(-13.335,9.525) E3(-12.065,9.525) E4(-10.795,9.525) E5(-9.525,9.525) E6(-8.255,9.525) E7(-6.985,9.525) E8(-5.715,9.525) E9(-4.445,9.525) E10(-3.175,9.525) E11(-1.905,9.525) E12(-0.635,9.525) E13(0.635,9.525) E14(1.905,9.525) E15(3.175,9.525) E16(4.445,9.525) E17(5.715,9.525) E18(6.985,9.525) E19(8.255,9.525) E20(9.525,9.525) E21(10.795,9.525) E22(12.065,9.525) E23(13.335,9.525) E24(14.605,9.525) F1(-14.605,8.255) F2(-13.335,8.255) F3(-12.065,8.255) F4(-10.795,8.255) F5(-9.525,8.255) F6(-8.255,8.255) F7(-6.985,8.255) F8(-5.715,8.255) F9(-4.445,8.255) F10(-3.175,8.255) F11(-1.905,8.255) F12(-0.635,8.255) F13(0.635,8.255) F14(1.905,8.255) F15(3.175,8.255) F16(4.445,8.255) F17(5.715,8.255) F18(6.985,8.255) F19(8.255,8.255) F20(9.525,8.255) F21(10.795,8.255) F22(12.065,8.255) F23(13.335,8.255) F24(14.605,8.255) G1(-14.605,6.985) G2(-13.335,6.985) G3(-12.065,6.985) G4(-10.795,6.985) G5(-9.525,6.985) G6(-8.255,6.985) G7(-6.985,6.985) G8(-5.715,6.985) G9(-4.445,6.985) G10(-3.175,6.985) G11(-1.905,6.985) G12(-0.635,6.985) G13(0.635,6.985) G14(1.905,6.985) G15(3.175,6.985) G16(4.445,6.985) G17(5.715,6.985) G18(6.985,6.985) G19(8.255,6.985) G20(9.525,6.985) G21(10.795,6.985) G22(12.065,6.985) G23(13.335,6.985) G24(14.605,6.985) H1(-14.605,5.715) H2(-13.335,5.715) H3(-12.065,5.715) H4(-10.795,5.715) H5(-9.525,5.715) H6(-8.255,5.715) H7(-6.985,5.715) H8(-5.715,5.715) H9(-4.445,5.715) H10(-3.175,5.715) H11(-1.905,5.715) H12(-0.635,5.715) H13(0.635,5.715) H14(1.905,5.715) H15(3.175,5.715) H16(4.445,5.715) H17(5.715,5.715) H18(6.985,5.715) H19(8.255,5.715) H20(9.525,5.715) H21(10.795,5.715) H22(12.065,5.715) H23(13.335,5.715) H24(14.605,5.715) J1(-14.605,4.445) J2(-13.335,4.445) J3(-12.065,4.445) J4(-10.795,4.445) J5(-9.525,4.445) J6(-8.255,4.445) J7(-6.985,4.445) J8(-5.715,4.445) J9(-4.445,4.445) J10(-3.175,4.445) J11(-1.905,4.445) J12(-0.635,4.445) J13(0.635,4.445) J14(1.905,4.445) J15(3.175,4.445) J16(4.445,4.445) J17(5.715,4.445) J18(6.985,4.445) J19(8.255,4.445) J20(9.525,4.445) J21(10.795,4.445) J22(12.065,4.445) J23(13.335,4.445) J24(14.605,4.445) K1(-14.605,3.175) K2(-13.335,3.175) K3(-12.065,3.175) K4(-10.795,3.175) K5(-9.525,3.175) K6(-8.255,3.175) K7(-6.985,3.175) K8(-5.715,3.175) K9(-4.445,3.175) K10(-3.175,3.175) K11(-1.905,3.175) K12(-0.635,3.175) K13(0.635,3.175) K14(1.905,3.175) K15(3.175,3.175) K16(4.445,3.175) K17(5.715,3.175) K18(6.985,3.175) K19(8.255,3.175) K20(9.525,3.175) K21(10.795,3.175) K22(12.065,3.175) K23(13.335,3.175) K24(14.605,3.175) L1(-14.605,1.905) L2(-13.335,1.905) L3(-12.065,1.905) L4(-10.795,1.905) L5(-9.525,1.905) L6(-8.255,1.905) L7(-6.985,1.905) L8(-5.715,1.905) L9(-4.445,1.905) L10(-3.175,1.905) L11(-1.905,1.905) L12(-0.635,1.905) L13(0.635,1.905) L14(1.905,1.905) L15(3.175,1.905) L16(4.445,1.905) L17(5.715,1.905) L18(6.985,1.905) L19(8.255,1.905) L20(9.525,1.905) L21(10.795,1.905) L22(12.065,1.905) L23(13.335,1.905) L24(14.605,1.905) M1(-14.605,0.635) M2(-13.335,0.635) M3(-12.065,0.635) M4(-10.795,0.635) M5(-9.525,0.635) M6(-8.255,0.635) M7(-6.985,0.635) M8(-5.715,0.635) M9(-4.445,0.635) M10(-3.175,0.635) M11(-1.905,0.635) M12(-0.635,0.635) M13(0.635,0.635) M14(1.905,0.635) M15(3.175,0.635) M16(4.445,0.635) M17(5.715,0.635) M18(6.985,0.635) M19(8.255,0.635) M20(9.525,0.635) M21(10.795,0.635) M22(12.065,0.635) M23(13.335,0.635) M24(14.605,0.635) N1(-14.605,-0.635) N2(-13.335,-0.635) N3(-12.065,-0.635) N4(-10.795,-0.635) N5(-9.525,-0.635) N6(-8.255,-0.635) N7(-6.985,-0.635) N8(-5.715,-0.635) N9(-4.445,-0.635) N10(-3.175,-0.635) N11(-1.905,-0.635) N12(-0.635,-0.635) N13(0.635,-0.635) N14(1.905,-0.635) N15(3.175,-0.635) N16(4.445,-0.635) N17(5.715,-0.635) N18(6.985,-0.635) N19(8.255,-0.635) N20(9.525,-0.635) N21(10.795,-0.635) N22(12.065,-0.635) N23(13.335,-0.635) N24(14.605,-0.635) P1(-14.605,-1.905) P2(-13.335,-1.905) P3(-12.065,-1.905) P4(-10.795,-1.905) P5(-9.525,-1.905) P6(-8.255,-1.905) P7(-6.985,-1.905) P8(-5.715,-1.905) P9(-4.445,-1.905) P10(-3.175,-1.905) P11(-1.905,-1.905) P12(-0.635,-1.905) P13(0.635,-1.905) P14(1.905,-1.905) P15(3.175,-1.905) P16(4.445,-1.905) P17(5.715,-1.905) P18(6.985,-1.905) P19(8.255,-1.905) P20(9.525,-1.905) P21(10.795,-1.905) P22(12.065,-1.905) P23(13.335,-1.905) P24(14.605,-1.905) R1(-14.605,-3.175) R2(-13.335,-3.175) R3(-12.065,-3.175) R4(-10.795,-3.175) R5(-9.525,-3.175) R6(-8.255,-3.175) R7(-6.985,-3.175) R8(-5.715,-3.175) R9(-4.445,-3.175) R10(-3.175,-3.175) R11(-1.905,-3.175) R12(-0.635,-3.175) R13(0.635,-3.175) R14(1.905,-3.175) R15(3.175,-3.175) R16(4.445,-3.175) R17(5.715,-3.175) R18(6.985,-3.175) R19(8.255,-3.175) R20(9.525,-3.175) R21(10.795,-3.175) R22(12.065,-3.175) R23(13.335,-3.175) R24(14.605,-3.175) T1(-14.605,-4.445) T2(-13.335,-4.445) T3(-12.065,-4.445) T4(-10.795,-4.445) T5(-9.525,-4.445) T6(-8.255,-4.445) T7(-6.985,-4.445) T8(-5.715,-4.445) T9(-4.445,-4.445) T10(-3.175,-4.445) T11(-1.905,-4.445) T12(-0.635,-4.445) T13(0.635,-4.445) T14(1.905,-4.445) T15(3.175,-4.445) T16(4.445,-4.445) T17(5.715,-4.445) T18(6.985,-4.445) T19(8.255,-4.445) T20(9.525,-4.445) T21(10.795,-4.445) T22(12.065,-4.445) T23(13.335,-4.445) T24(14.605,-4.445) U1(-14.605,-5.715) U2(-13.335,-5.715) U3(-12.065,-5.715) U4(-10.795,-5.715) U5(-9.525,-5.715) U6(-8.255,-5.715) U7(-6.985,-5.715) U8(-5.715,-5.715) U9(-4.445,-5.715) U10(-3.175,-5.715) U11(-1.905,-5.715) U12(-0.635,-5.715) U13(0.635,-5.715) U14(1.905,-5.715) U15(3.175,-5.715) U16(4.445,-5.715) U17(5.715,-5.715) U18(6.985,-5.715) U19(8.255,-5.715) U20(9.525,-5.715) U21(10.795,-5.715) U22(12.065,-5.715) U23(13.335,-5.715) U24(14.605,-5.715) V1(-14.605,-6.985) V2(-13.335,-6.985) V3(-12.065,-6.985) V4(-10.795,-6.985) V5(-9.525,-6.985) V6(-8.255,-6.985) V7(-6.985,-6.985) V8(-5.715,-6.985) V9(-4.445,-6.985) V10(-3.175,-6.985) V11(-1.905,-6.985) V12(-0.635,-6.985) V13(0.635,-6.985) V14(1.905,-6.985) V15(3.175,-6.985) V16(4.445,-6.985) V17(5.715,-6.985) V18(6.985,-6.985) V19(8.255,-6.985) V20(9.525,-6.985) V21(10.795,-6.985) V22(12.065,-6.985) V23(13.335,-6.985) V24(14.605,-6.985) W1(-14.605,-8.255) W2(-13.335,-8.255) W3(-12.065,-8.255) W4(-10.795,-8.255) W5(-9.525,-8.255) W6(-8.255,-8.255) W7(-6.985,-8.255) W8(-5.715,-8.255) W9(-4.445,-8.255) W10(-3.175,-8.255) W11(-1.905,-8.255) W12(-0.635,-8.255) W13(0.635,-8.255) W14(1.905,-8.255) W15(3.175,-8.255) W16(4.445,-8.255) W17(5.715,-8.255) W18(6.985,-8.255) W19(8.255,-8.255) W20(9.525,-8.255) W21(10.795,-8.255) W22(12.065,-8.255) W23(13.335,-8.255) W24(14.605,-8.255) Y1(-14.605,-9.525) Y2(-13.335,-9.525) Y3(-12.065,-9.525) Y4(-10.795,-9.525) Y5(-9.525,-9.525) Y6(-8.255,-9.525) Y7(-6.985,-9.525) Y8(-5.715,-9.525) Y9(-4.445,-9.525) Y10(-3.175,-9.525) Y11(-1.905,-9.525) Y12(-0.635,-9.525) Y13(0.635,-9.525) Y14(1.905,-9.525) Y15(3.175,-9.525) Y16(4.445,-9.525) Y17(5.715,-9.525) Y18(6.985,-9.525) Y19(8.255,-9.525) Y20(9.525,-9.525) Y21(10.795,-9.525) Y22(12.065,-9.525) Y23(13.335,-9.525) Y24(14.605,-9.525)
Top Overlay:
  circle w0.25: c-16.15,14.605 r0.125
  region: -14.7,15.5 -15.5,14.7 -15.5,15.5
  lines w0.2: -15.5,14.7 -14.7,15.5 ; -15.5,-15.5 -15.5,15.5 15.5,15.5 15.5,-15.5 -15.5,-15.5
Mechanical 13:
  lines w0.1: -15.5,-15.5 -15.5,15.5 15.5,15.5 15.5,-15.5 -15.5,-15.5
Mechanical 15:
  lines w0.1: -0.5,0 0.5,0 ; 0,-0.5 0,0.5 ; -16.5,-16.5 -16.5,16.5 16.5,16.5 16.5,-16.5 -16.5,-16.5
3D body: height 2.6, standoff 0, extent -15.5,-15.5 15.5,15.5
